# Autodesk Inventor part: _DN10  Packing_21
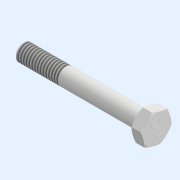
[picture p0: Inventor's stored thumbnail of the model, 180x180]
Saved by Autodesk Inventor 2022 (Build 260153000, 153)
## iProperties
Created: 2021-12
Part Number: _DN10  Packing_21
Material: Generico
Document SubType Name: Modeling
Designer: admin
Density: 1 g/cm^3
Appearance: Default
Author: admin
Revision Number: NONE
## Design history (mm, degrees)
feature "_DN10  Packing"
feature "Filettatura1" dims "d0" = 15, "d1" = 0
node "Solido1"
